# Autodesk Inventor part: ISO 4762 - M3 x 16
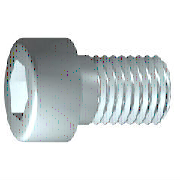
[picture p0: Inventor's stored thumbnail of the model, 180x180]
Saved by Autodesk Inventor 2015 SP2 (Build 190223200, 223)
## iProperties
IsCustomPart: 0
Created: 2012-02
Part Number: ISO 4762 - M3 x 16
Material: Edelstahl, 440C
Description: Innensechskantschraube
Document SubType Name: Modeling
Standard: ISO 4762
Designer: Hübner
Standard Revision: 1998
Standards Organization: DIN
Language: de-DE
Size Designation: M3 x 16
Categories: <MemberInstance><Categories><Category DisplayName="Verbindungselemente" InternalName="e4da775c-781d-43d5-af7c-5136215cf5a6" Mnemonic="FSTN"><Category DisplayNam
Density: 7.75 g/cm^3
Appearance: Halbpoliert
Author: Hübner
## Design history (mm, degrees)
sketch "Skizze1"
  geometry: L1 (-0.867, 0)-(16, 0); L2 (16, 0)-(16, 1.5); L3 (16, 1.5)-(1.25, 1.5); L4 (1.25, 1.5)-(0.943, 1.5); L5 (0.943, 1.5)-(0, 1.5); L6 (0, 1.5)-(0, 2.75); L7 (0, 2.75)-(-3, 2.75); L8 (-3, 2.75)-(-3, 1.443); L9 (-3, 1.443)-(-1.7, 1.443); L10 (-1.7, 1.443)-(-0.867, 0); L11 (-6.8, 0)-(19.8, 0) reference; L12 (0, -0.55)-(0, 3.3) reference; L13 (1.25, 1.5)-(0, 1.5)
  constraints: 22 end point, 6 parallel, 2 collinear, 2 perpendicular, 1 horizontal, 1 point on line
  dimensions: "d1" = 14.75 distance from line of L3.end L2 (= GEL); "d2" = 0.30683 distance of L4.end L3.end (computed from GAL); "d3" = 3 distance between parallel lines of L8 L6 (= KOH); "d4" = 1.3 distance of L8.end L9.end (= INTI); "d5" = 60 deg angle of L10 L1; "d6" = 3 diameter of L3 L1 (= GD); "d7" = 3 diameter of L5 L1 (= BDM); "d8" = 2.88675 diameter of L9 L1 (= 1.1547 x SW); "d9" = 5.5 diameter of L7 L1 (= KOD); "d26" = 16 distance between parallel lines of L12 L2 (= NLG)
revolve "Körper" sketch "Skizze1" stored, may be unused: angle "d10" = 90 deg
sketch "Skizze2"
  geometry: L1 (0, -3.85)-(0, 3.85) reference; L2 (-3.85, 0)-(3.85, 0) reference; L3 (1.443, 0)-(0.722, -1.25); L4 (0.722, -1.25)-(-0.722, -1.25); L5 (-0.722, -1.25)-(-1.443, 0); L6 (-1.443, 0)-(-0.722, 1.25); L7 (-0.722, 1.25)-(0.722, 1.25); L8 (0.722, 1.25)-(1.443, 0); 2 further points
  constraints: 12 end point, 1 coincident, 1 horizontal alignment, 1 point on line, 12 other
extrude "Loch" join sketch "Skizze2" stored distance "d11" = 10; taper "d12" = 0 deg
workplane "Work Plane1"
fillet "Fillet2" dims "d30" = 0.1 (= R)
body "Solid1"
fillet "Rundung1" dims "d17" = 0.3 (= RR)
feature "Gewinde" dims "d13" = 14.75 (= GEL), "d14" = 0
chamfer "Fase1" distance "d15" = 0.30673 (= -0.5 x SPD + 0.5 x GD); stored, may be unused: second distance "d16" = 0.30673 (= GUL), angle "d27" = 45 deg
other parameters: "GD" = 3 [user parameter; used in 2 equation terms], "NLG" = 16 [user parameter; used in 1 equation term], "GEL" = 14.75 [user parameter; used in 2 equation terms], "KOD" = 5.5 [user parameter; used in 1 equation term], "KOH" = 3 [user parameter; used in 1 equation term], "INTI" = 1.3 [user parameter; used in 1 equation term], "GAL" = 0.30673 (= 0.61345 x PTC) [user parameter; used in 1 equation term], "GUL" = 0.30673 (= 0.61345 x PTC) [user parameter; used in 1 equation term], "BDM" = 3 (= NND) [user parameter; used in 1 equation term], "SW" = 2.5 [user parameter; used in 2 equation terms], "RR" = 0.3 [user parameter; used in 1 equation term], "SPD" = 2.38655 (= NND - 1.2269 x PTC) [user parameter; used in 1 equation term], "d19" = 0, "d28" = 0, "d29" = 0, "R" = 0.1 [user parameter; used in 1 equation term], "TOA" = 30 deg [user parameter], "GD1" = 2.38655 (= THREADDIA - 1.2269 x PTC) [user parameter], "THREADDIA" = 3 [user parameter; used in 1 equation term], "FAWI" = 45 deg [user parameter], "PTC" = 0.5 [user parameter; used in 5 equation terms], "NND" = 3 [user parameter; used in 2 equation terms], "E0" = 2.8875 (= 1.155 x SW) [user parameter]
